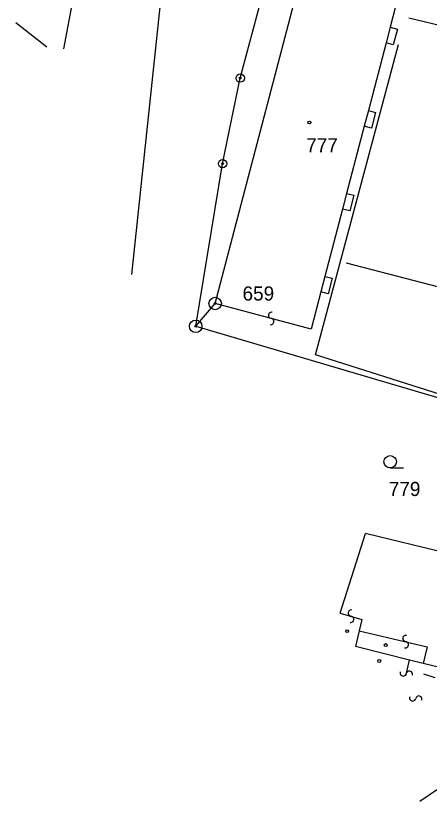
# Model space of a CAD drawing. Extents: x -469926 to -462499, y -1098642 to -1092733.
# Drawn here: x -465640.3 to -465590.7, y -1095042.6 to -1094948.2 of the extents above; entities that cross this region are included whole.
import ezdxf

# ---------------------------------------------------------------- set-up
doc = ezdxf.new("R2010")
doc.units = 0
for name, color, linetype in [('Vrstva 1', 7, 'Continuous'), ('Vrstva 14', 7, 'Continuous'), ('Vrstva 16', 7, 'Continuous'), ('Vrstva 24', 7, 'Continuous'), ('Vrstva 25', 7, 'Continuous'), ('Vrstva 4', 7, 'Continuous'), ('Vrstva 50', 7, 'Continuous'), ('Vrstva 51', 7, 'Continuous'), ('Vrstva 6', 7, 'Continuous')]:
    doc.layers.add(name, color=color, linetype=linetype)

msp = doc.modelspace()

# ---------------------------------------------------------------- linework, layer by layer
at = {"layer": 'Vrstva 1'}
for p, q in [((-465623.08, -1094890.59), (-465634.59, -1094952.18)), ((-465613.36, -1094955.68), (-465609.41, -1094941)), ((-465636.58, -1094951.98), (-465640.32, -1094949.03)), ((-465615.48, -1094965.97), (-465613.36, -1094955.68)), ((-465618.7, -1094985.52), (-465615.48, -1094965.97)), ((-465618.7, -1094985.52), (-465568.37, -1095000.37)), ((-465601.35, -1095019.99), (-465598.3, -1095010.43)), ((-465576.07, -1095015.86), (-465598.3, -1095010.43)), ((-465599.19, -1095024.09), (-465599.51, -1095024.01)), ((-465593.03, -1095025.66), (-465599.19, -1095024.09)), ((-465591.38, -1095026.05), (-465593.03, -1095025.66)), ((-465589.54, -1095026.5), (-465591.38, -1095026.05)), ((-465591.787, -1095042.615), (-465586.468, -1095038.964)), ((-465591.787, -1095042.615), (-465586.468, -1095038.964))]:
    msp.add_line(p, q, dxfattribs=at)
at = {"layer": 'Vrstva 14'}
for p, q in [((-465593.11, -1094948.433), (-465569.032, -1094954.209)), ((-465576.707, -1094984.146), (-465600.587, -1094977.936))]:
    msp.add_line(p, q, dxfattribs=at)
at = {"layer": 'Vrstva 16'}
for p, q in [((-465604.328, -1094988.937), (-465594.349, -1094951.63)), ((-465567.282, -1095000.775), (-465604.328, -1094988.937))]:
    msp.add_line(p, q, dxfattribs=at)
at = {"layer": 'Vrstva 24'}
for centre, radius in [((-465613.36, -1094955.68), 0.5), ((-465613.36, -1094955.68), 0.1), ((-465615.48, -1094965.97), 0.5), ((-465615.48, -1094965.97), 0.1), ((-465616.37, -1094982.77), 0.75), ((-465616.37, -1094982.77), 0.1), ((-465618.7, -1094985.52), 0.75), ((-465618.7, -1094985.52), 0.1)]:
    msp.add_circle(centre, radius, dxfattribs=at)
at = {"layer": 'Vrstva 25'}
msp.add_line((-465595.35, -1095002.55), (-465593.75, -1095002.55), dxfattribs=at)
for centre, radius in [((-465605.05, -1094961.02), 0.175), ((-465595.35, -1095001.8), 0.75), ((-465600.52, -1095022.17), 0.175), ((-465595.88, -1095023.84), 0.175), ((-465596.66, -1095025.75), 0.175)]:
    msp.add_circle(centre, radius, dxfattribs=at)
at = {"layer": 'Vrstva 4'}
for p, q in [((-465616.37, -1094982.77), (-465605.7, -1094942.11)), ((-465594.2, -1094945.11), (-465595.36, -1094949.57)), ((-465595.36, -1094949.57), (-465595.85, -1094951.45)), ((-465595.36, -1094949.57), (-465594.49, -1094949.8)), ((-465594.49, -1094949.8), (-465594.98, -1094951.68)), ((-465595.85, -1094951.45), (-465597.97, -1094959.57)), ((-465594.98, -1094951.68), (-465595.85, -1094951.45)), ((-465597.97, -1094959.57), (-465598.47, -1094961.47)), ((-465597.97, -1094959.57), (-465597.1, -1094959.8)), ((-465597.1, -1094959.8), (-465597.6, -1094961.7)), ((-465598.47, -1094961.47), (-465600.58, -1094969.54)), ((-465597.6, -1094961.7), (-465598.47, -1094961.47)), ((-465600.58, -1094969.54), (-465601.07, -1094971.42)), ((-465600.58, -1094969.54), (-465599.71, -1094969.77)), ((-465599.71, -1094969.77), (-465600.2, -1094971.64)), ((-465601.07, -1094971.42), (-465603.18, -1094979.52)), ((-465600.2, -1094971.64), (-465601.07, -1094971.42)), ((-465603.18, -1094979.52), (-465603.67, -1094981.38)), ((-465603.18, -1094979.52), (-465602.31, -1094979.74)), ((-465602.31, -1094979.74), (-465602.8, -1094981.61)), ((-465603.67, -1094981.38), (-465604.84, -1094985.86)), ((-465602.8, -1094981.61), (-465603.67, -1094981.38)), ((-465618.7, -1094985.52), (-465616.37, -1094982.77)), ((-465604.84, -1094985.86), (-465616.37, -1094982.77)), ((-465601.35, -1095019.99), (-465598.75, -1095020.75)), ((-465598.75, -1095020.75), (-465599.06, -1095022.11)), ((-465599.06, -1095022.11), (-465599.51, -1095024.01)), ((-465599.06, -1095022.11), (-465590.89, -1095024.03)), ((-465590.89, -1095024.03), (-465591.38, -1095026.05)), ((-465593.48, -1095027.53), (-465593.03, -1095025.66)), ((-465589.95, -1095027.78), (-465591.32, -1095027.33))]:
    msp.add_line(p, q, dxfattribs=at)
at = {"layer": 'Vrstva 51'}
for centre, radius, start, end in [((-465609.595, -1094984.199), 0.376, 76.40036, 262.71149), ((-465609.686, -1094984.947), 0.377, 255.72432, 83.38753), ((-465600.022, -1095019.993), 0.376, 78.46036, 264.77149), ((-465600.086, -1095020.744), 0.377, 257.78432, 85.44753), ((-465593.467, -1095023.041), 0.376, 78.46036, 264.77149), ((-465593.532, -1095023.792), 0.377, 257.78432, 85.44753), ((-465593.784, -1095027.186), 0.376, 161.99036, 348.30149), ((-465593.046, -1095027.334), 0.377, 341.31432, 168.97753), ((-465592.648, -1095030.185), 0.376, 161.99036, 348.30149), ((-465591.91, -1095030.333), 0.377, 341.31432, 168.97753)]:
    msp.add_arc(centre, radius, start, end, dxfattribs=at)
at = {"layer": 'Vrstva 6'}
msp.add_line((-465621.582, -1094933.344), (-465626.402, -1094979.279), dxfattribs=at)

# ---------------------------------------------------------------- texts
at = {"layer": 'Vrstva 50'}
for s, p in [('777', (-465605.435, -1094964.61)), ('659', (-465613.079, -1094982.42)), ('779', (-465595.514, -1095005.92))]:
    msp.add_text(s, height=1.7, dxfattribs=at).set_placement(p)

doc.saveas('drawing.dxf')
